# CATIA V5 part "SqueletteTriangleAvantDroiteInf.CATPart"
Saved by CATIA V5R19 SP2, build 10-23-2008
Part number: SqueletteTriangleAvantDroiteInf
Bounding box of the stored display mesh (mm): x 617.517 to 667.517, y 59.099 to 148.642, z -240.762 to -220.798
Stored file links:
  E:\Mes documents\03_Ressources pédagogiques\01_Catia\Buggy Dassault\SchemaCinematiqueFinal\SqueletteTriangleAvantDroiteInf.CATPart
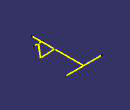
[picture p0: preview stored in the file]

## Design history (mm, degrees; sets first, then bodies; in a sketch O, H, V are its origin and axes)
AxisSystem1: origin (0, 0, 0), X (1, 0, 0), Y (0, 1, 0), Z (0, 0, 1)
Set1
  Point1 to Point6: stored without definition
  Line1: stored without definition
  Point7: stored without definition
  Line2: stored without definition
  Point8: stored without definition
  Point9: stored without definition
  Line3 to Line6: stored without definition
  MultiSel1
Body1 (main body)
